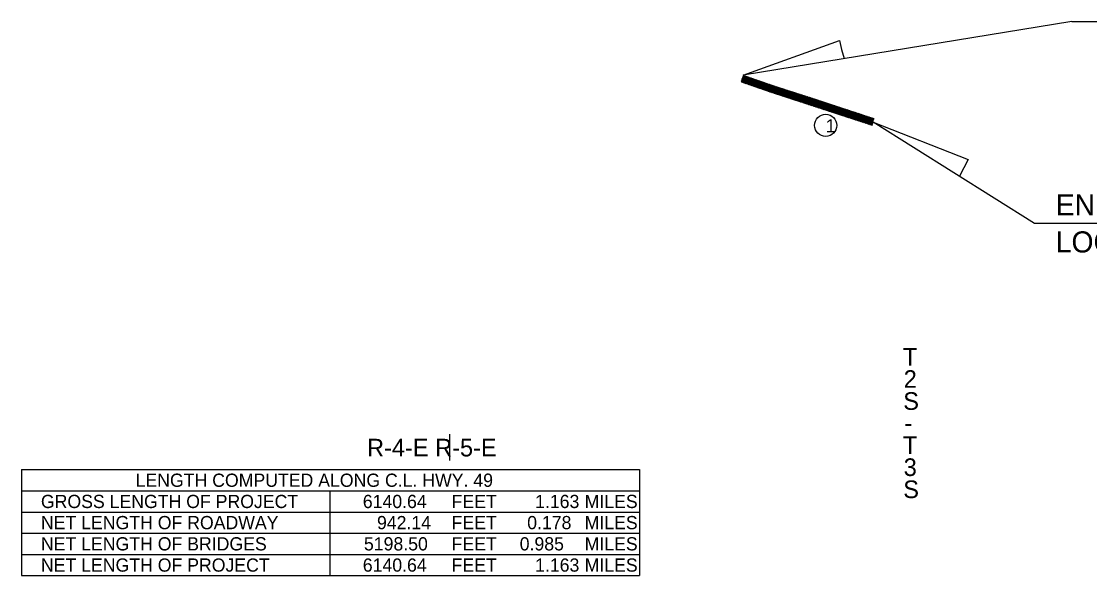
# Model space of a CAD drawing. Extents: x -712 to 3943, y 73 to 2823.
# Drawn here: x 1396 to 2609, y 73 to 702 of the extents above; entities that cross this region are included whole.
import ezdxf

# ---------------------------------------------------------------- set-up
doc = ezdxf.new("R2010")
doc.units = 0
for name, color, linetype in [('2', 7, 'Continuous'), ('3', 7, 'Continuous'), ('Default', 7, 'Continuous'), ('S_MISC_BOUNDARY', 7, 'Continuous')]:
    doc.layers.add(name, color=color, linetype=linetype)

msp = doc.modelspace()

# ---------------------------------------------------------------- linework, layer by layer
at = {"layer": '2'}
msp.add_circle((2309.2, 584.4), 12.6, dxfattribs=at)
at = {"layer": '3'}
for p, q in [((1396.1, 193.6), (1396.1, 73.3)), ((1396.1, 193.6), (2097.8, 193.6)), ((2097.8, 193.6), (2097.8, 73.3)), ((1396.1, 169.6), (2097.8, 169.6)), ((1746.3, 169.6), (1746.3, 73.3)), ((1396.1, 145.5), (2097.8, 145.5)), ((1396.1, 121.4), (2097.8, 121.4)), ((1396.1, 97.4), (2097.8, 97.4)), ((1396.1, 73.3), (2097.8, 73.3))]:
    msp.add_line(p, q, dxfattribs=at)
at = {"layer": 'Default'}
for p, q in [((2863.6, 473.1), (2546.3, 473.1)), ((1882.1, 233.7), (1882.1, 204))]:
    msp.add_line(p, q, dxfattribs=at)
for points in [[(2588.6, 702.5), (2215.6, 641.5), (2324.8, 680.8), (2327.2, 670.6), (2330, 660.2)], [(2588.6, 702.5), (2938.9, 702.3)], [(2546.3, 473.1), (2363, 588.2), (2470.9, 545.5), (2466, 536.2), (2461.2, 526.6)]]:
    msp.add_lwpolyline(points, dxfattribs=at)
at = {"layer": 'S_MISC_BOUNDARY'}
for p, q in [((2213, 633.6), (2219.5, 640.1)), ((2213.2, 634.5), (2219, 640.3)), ((2213.5, 633.4), (2220.1, 639.9)), ((2213.6, 635.6), (2218.5, 640.5)), ((2214, 636.7), (2218, 640.7)), ((2214, 633.2), (2220.6, 639.7)), ((2214.3, 637.7), (2217.4, 640.8)), ((2214.6, 633), (2221.1, 639.6)), ((2214.7, 638.8), (2216.9, 641)), ((2215.1, 639.9), (2216.4, 641.2)), ((2215.1, 632.8), (2221.6, 639.4)), ((2215.5, 641), (2215.9, 641.4)), ((2215.6, 632.6), (2222.2, 639.2)), ((2216.1, 632.5), (2222.7, 639)), ((2216.7, 632.3), (2223.2, 638.8)), ((2217.2, 632.1), (2223.7, 638.6)), ((2217.7, 631.9), (2224.3, 638.5)), ((2218.2, 631.7), (2224.8, 638.3)), ((2218.8, 631.6), (2225.3, 638.1)), ((2219.3, 631.4), (2225.8, 637.9)), ((2219.8, 631.2), (2226.3, 637.7)), ((2220.3, 631), (2226.9, 637.6)), ((2220.9, 630.8), (2227.4, 637.4)), ((2221.4, 630.6), (2227.9, 637.2)), ((2221.9, 630.5), (2228.4, 637)), ((2222.4, 630.3), (2229, 636.8)), ((2223, 630.1), (2229.5, 636.6)), ((2223.5, 629.9), (2230, 636.5)), ((2224, 629.7), (2230.5, 636.3)), ((2224.5, 629.5), (2231.1, 636.1)), ((2225, 629.4), (2231.6, 635.9)), ((2225.6, 629.2), (2232.1, 635.7)), ((2226.1, 629), (2232.6, 635.5)), ((2226.6, 628.8), (2233.2, 635.4)), ((2227.1, 628.6), (2233.7, 635.2)), ((2227.7, 628.4), (2234.2, 635)), ((2228.2, 628.3), (2234.7, 634.8)), ((2228.7, 628.1), (2235.3, 634.6)), ((2229.2, 627.9), (2235.8, 634.4)), ((2229.8, 627.7), (2236.3, 634.3)), ((2230.3, 627.5), (2236.8, 634.1)), ((2230.8, 627.4), (2237.4, 633.9)), ((2231.3, 627.2), (2237.9, 633.7)), ((2231.9, 627), (2238.4, 633.5)), ((2232.4, 626.8), (2238.9, 633.4)), ((2232.9, 626.6), (2239.5, 633.2)), ((2233.4, 626.4), (2240, 633)), ((2234, 626.3), (2240.5, 632.8)), ((2234.5, 626.1), (2241, 632.6)), ((2235, 625.9), (2241.6, 632.4)), ((2235.5, 625.7), (2242.1, 632.3)), ((2236.1, 625.5), (2242.6, 632.1)), ((2236.6, 625.3), (2243.1, 631.9)), ((2237.1, 625.2), (2243.7, 631.7)), ((2237.6, 625), (2244.2, 631.5)), ((2238.2, 624.8), (2244.7, 631.3)), ((2238.7, 624.6), (2245.2, 631.2)), ((2239.2, 624.4), (2245.8, 631)), ((2239.7, 624.3), (2246.3, 630.8)), ((2240.3, 624.1), (2246.8, 630.6)), ((2240.8, 623.9), (2247.3, 630.4)), ((2241.3, 623.7), (2247.9, 630.3)), ((2241.8, 623.5), (2248.4, 630.1)), ((2242.4, 623.3), (2248.9, 629.9)), ((2242.9, 623.2), (2249.4, 629.7)), ((2243.4, 623), (2250, 629.5)), ((2243.9, 622.8), (2250.5, 629.4)), ((2244.5, 622.6), (2251, 629.2)), ((2245, 622.4), (2251.6, 629)), ((2245.5, 622.2), (2252.1, 628.8)), ((2246, 622.1), (2252.6, 628.7)), ((2246.6, 621.9), (2253.2, 628.5)), ((2247.1, 621.7), (2253.7, 628.3)), ((2247.6, 621.5), (2254.2, 628.2)), ((2248.2, 621.4), (2254.8, 628)), ((2248.7, 621.2), (2255.3, 627.8)), ((2249.2, 621), (2255.8, 627.6)), ((2249.8, 620.8), (2256.4, 627.5)), ((2250.3, 620.7), (2256.9, 627.3)), ((2250.8, 620.5), (2257.5, 627.1)), ((2251.4, 620.3), (2258, 626.9)), ((2251.9, 620.1), (2258.5, 626.8)), ((2252.4, 620), (2259.1, 626.6)), ((2253, 619.8), (2259.6, 626.4)), ((2253.5, 619.6), (2260.1, 626.3)), ((2254, 619.4), (2260.7, 626.1)), ((2254.6, 619.3), (2261.2, 625.9)), ((2255.1, 619.1), (2261.7, 625.7)), ((2255.6, 618.9), (2262.3, 625.6)), ((2256.1, 618.7), (2262.8, 625.4)), ((2256.7, 618.6), (2263.3, 625.2)), ((2257.2, 618.4), (2263.9, 625.1)), ((2257.7, 618.2), (2264.4, 624.9)), ((2258.3, 618), (2264.9, 624.7)), ((2258.8, 617.9), (2265.5, 624.5)), ((2259.3, 617.7), (2266, 624.4)), ((2259.9, 617.5), (2266.5, 624.2)), ((2260.4, 617.3), (2267.1, 624)), ((2260.9, 617.2), (2267.6, 623.8)), ((2261.5, 617), (2268.2, 623.7)), ((2262, 616.8), (2268.7, 623.5)), ((2262.5, 616.7), (2269.2, 623.3)), ((2263.1, 616.5), (2269.8, 623.2)), ((2263.6, 616.3), (2270.3, 623)), ((2264.1, 616.1), (2270.8, 622.8)), ((2264.7, 616), (2271.4, 622.6)), ((2265.2, 615.8), (2271.9, 622.5)), ((2265.7, 615.6), (2272.4, 622.3)), ((2266.3, 615.4), (2273, 622.1)), ((2266.8, 615.3), (2273.5, 622)), ((2267.3, 615.1), (2274, 621.8)), ((2267.9, 614.9), (2274.6, 621.6)), ((2268.4, 614.7), (2275.1, 621.4)), ((2268.9, 614.6), (2275.6, 621.3)), ((2269.5, 614.4), (2276.2, 621.1)), ((2270, 614.2), (2276.7, 620.9)), ((2270.5, 614), (2277.2, 620.7)), ((2271.1, 613.9), (2277.8, 620.6)), ((2271.6, 613.7), (2278.3, 620.4)), ((2272.1, 613.5), (2278.8, 620.2)), ((2272.7, 613.3), (2279.4, 620.1)), ((2273.2, 613.2), (2279.9, 619.9)), ((2273.7, 613), (2280.5, 619.7)), ((2274.3, 612.8), (2281, 619.5)), ((2274.8, 612.6), (2281.5, 619.4)), ((2275.3, 612.5), (2282.1, 619.2)), ((2275.9, 612.3), (2282.6, 619)), ((2276.4, 612.1), (2283.1, 618.9)), ((2276.9, 612), (2283.7, 618.7)), ((2277.5, 611.8), (2284.2, 618.5)), ((2278, 611.6), (2284.7, 618.3)), ((2278.5, 611.4), (2285.3, 618.2)), ((2279.1, 611.3), (2285.8, 618)), ((2279.6, 611.1), (2286.3, 617.8)), ((2280.1, 610.9), (2286.9, 617.6)), ((2280.7, 610.7), (2287.4, 617.5)), ((2281.2, 610.6), (2287.9, 617.3)), ((2281.7, 610.4), (2288.5, 617.1)), ((2282.3, 610.2), (2289, 617)), ((2282.8, 610), (2289.5, 616.8)), ((2283.3, 609.9), (2290.1, 616.6)), ((2283.9, 609.7), (2290.6, 616.4)), ((2284.4, 609.5), (2291.2, 616.3)), ((2284.9, 609.3), (2291.7, 616.1)), ((2285.5, 609.2), (2292.2, 615.9)), ((2286, 609), (2292.8, 615.8)), ((2286.5, 608.8), (2293.3, 615.6)), ((2287.1, 608.6), (2293.8, 615.4)), ((2287.6, 608.5), (2294.4, 615.2)), ((2288.1, 608.3), (2294.9, 615.1)), ((2288.7, 608.1), (2295.4, 614.9)), ((2289.2, 607.9), (2296, 614.7)), ((2289.7, 607.8), (2296.5, 614.5)), ((2290.3, 607.6), (2297, 614.4)), ((2290.8, 607.4), (2297.6, 614.2)), ((2291.3, 607.2), (2298.1, 614)), ((2291.9, 607.1), (2298.6, 613.8)), ((2292.4, 606.9), (2299.2, 613.7)), ((2292.9, 606.7), (2299.7, 613.5)), ((2293.5, 606.6), (2300.2, 613.3)), ((2294, 606.4), (2300.8, 613.1)), ((2294.5, 606.2), (2301.3, 613)), ((2295.1, 606), (2301.8, 612.8)), ((2295.6, 605.9), (2302.3, 612.6)), ((2296.1, 605.7), (2302.9, 612.4)), ((2296.7, 605.5), (2303.4, 612.3)), ((2297.2, 605.3), (2303.9, 612.1)), ((2297.7, 605.2), (2304.5, 611.9)), ((2298.3, 605), (2305, 611.7)), ((2298.8, 604.8), (2305.5, 611.6)), ((2299.3, 604.6), (2306.1, 611.4)), ((2299.9, 604.5), (2306.6, 611.2)), ((2300.4, 604.3), (2307.1, 611)), ((2300.9, 604.1), (2307.7, 610.9)), ((2301.5, 603.9), (2308.2, 610.7)), ((2302, 603.8), (2308.7, 610.5)), ((2302.5, 603.6), (2309.3, 610.3)), ((2303.1, 603.4), (2309.8, 610.2)), ((2303.6, 603.2), (2310.3, 610)), ((2304.1, 603.1), (2310.9, 609.8)), ((2304.7, 602.9), (2311.4, 609.6)), ((2305.2, 602.7), (2311.9, 609.5)), ((2305.7, 602.5), (2312.4, 609.3)), ((2306.2, 602.4), (2313, 609.1)), ((2306.8, 602.2), (2313.5, 608.9)), ((2307.3, 602), (2314, 608.8)), ((2307.8, 601.9), (2314.6, 608.6)), ((2308.4, 601.7), (2315.1, 608.4)), ((2308.9, 601.5), (2315.6, 608.2)), ((2309.4, 601.3), (2316.2, 608.1)), ((2310, 601.2), (2316.7, 607.9)), ((2310.5, 601), (2317.2, 607.7)), ((2311, 600.8), (2317.8, 607.5)), ((2311.6, 600.6), (2318.3, 607.4)), ((2312.1, 600.5), (2318.8, 607.2)), ((2312.6, 600.3), (2319.4, 607)), ((2313.2, 600.1), (2319.9, 606.8)), ((2313.7, 599.9), (2320.4, 606.6)), ((2314.2, 599.8), (2321, 606.5)), ((2314.8, 599.6), (2321.5, 606.3)), ((2315.3, 599.4), (2322, 606.1)), ((2315.8, 599.2), (2322.5, 605.9)), ((2316.4, 599.1), (2323.1, 605.8)), ((2316.9, 598.9), (2323.6, 605.6)), ((2317.4, 598.7), (2324.1, 605.4)), ((2318, 598.5), (2324.7, 605.2)), ((2318.5, 598.4), (2325.2, 605.1)), ((2319, 598.2), (2325.7, 604.9)), ((2319.6, 598), (2326.3, 604.7)), ((2320.1, 597.8), (2326.8, 604.5)), ((2320.6, 597.7), (2327.3, 604.4)), ((2321.2, 597.5), (2327.9, 604.2)), ((2321.7, 597.3), (2328.4, 604)), ((2322.2, 597.2), (2328.9, 603.8)), ((2322.8, 597), (2329.5, 603.7)), ((2323.3, 596.8), (2330, 603.5)), ((2323.8, 596.6), (2330.5, 603.3)), ((2324.4, 596.5), (2331.1, 603.1)), ((2324.9, 596.3), (2331.6, 603)), ((2325.4, 596.1), (2332.1, 602.8)), ((2326, 595.9), (2332.7, 602.6)), ((2326.5, 595.8), (2333.2, 602.4)), ((2327, 595.6), (2333.7, 602.3)), ((2327.6, 595.4), (2334.2, 602.1)), ((2328.1, 595.2), (2334.8, 601.9)), ((2328.6, 595.1), (2335.3, 601.7)), ((2329.2, 594.9), (2335.8, 601.6)), ((2329.7, 594.7), (2336.4, 601.4)), ((2330.2, 594.5), (2336.9, 601.2)), ((2330.8, 594.4), (2337.4, 601)), ((2331.3, 594.2), (2338, 600.9)), ((2331.8, 594), (2338.5, 600.7)), ((2332.4, 593.8), (2339, 600.5)), ((2332.9, 593.7), (2339.6, 600.3)), ((2333.4, 593.5), (2340.1, 600.2)), ((2334, 593.3), (2340.6, 600)), ((2334.5, 593.1), (2341.2, 599.8)), ((2335, 593), (2341.7, 599.6)), ((2335.6, 592.8), (2342.2, 599.5)), ((2336.1, 592.6), (2342.8, 599.3)), ((2336.6, 592.4), (2343.3, 599.1)), ((2337.2, 592.3), (2343.8, 598.9)), ((2337.7, 592.1), (2344.3, 598.8)), ((2338.2, 591.9), (2344.9, 598.6)), ((2338.8, 591.8), (2345.4, 598.4)), ((2339.3, 591.6), (2345.9, 598.2)), ((2339.8, 591.4), (2346.5, 598.1)), ((2340.4, 591.2), (2347, 597.9)), ((2340.9, 591.1), (2347.5, 597.7)), ((2341.4, 590.9), (2348.1, 597.5)), ((2342, 590.7), (2348.6, 597.4)), ((2342.5, 590.5), (2349.1, 597.2)), ((2343, 590.4), (2349.7, 597)), ((2343.6, 590.2), (2350.2, 596.8)), ((2344.1, 590), (2350.7, 596.6)), ((2344.6, 589.8), (2351.3, 596.5)), ((2345.2, 589.7), (2351.8, 596.3)), ((2345.7, 589.5), (2352.3, 596.1)), ((2346.2, 589.3), (2352.9, 595.9)), ((2346.8, 589.1), (2353.4, 595.8)), ((2347.3, 589), (2353.9, 595.6)), ((2347.8, 588.8), (2354.5, 595.4)), ((2348.4, 588.6), (2355, 595.2)), ((2348.9, 588.4), (2355.5, 595.1)), ((2349.4, 588.3), (2356, 594.9)), ((2350, 588.1), (2356.6, 594.7)), ((2350.5, 587.9), (2357.1, 594.5)), ((2351, 587.7), (2357.6, 594.4)), ((2351.6, 587.6), (2358.2, 594.2)), ((2352.1, 587.4), (2358.7, 594)), ((2352.6, 587.2), (2359.2, 593.8)), ((2353.2, 587.1), (2359.8, 593.7)), ((2353.7, 586.9), (2360.3, 593.5)), ((2354.2, 586.7), (2360.8, 593.3)), ((2354.8, 586.5), (2361.4, 593.1)), ((2355.3, 586.4), (2361.9, 593)), ((2355.8, 586.2), (2362.4, 592.8)), ((2356.3, 586), (2363, 592.6)), ((2356.9, 585.8), (2363.5, 592.4)), ((2357.4, 585.7), (2364, 592.2)), ((2357.9, 585.5), (2363.7, 591.3)), ((2358.5, 585.3), (2363.5, 590.3)), ((2359, 585.1), (2363.2, 589.3)), ((2359.5, 585), (2363, 588.4)), ((2360.1, 584.8), (2362.7, 587.4)), ((2360.6, 584.6), (2362.5, 586.5)), ((2361.1, 584.4), (2362.2, 585.5)), ((2361.7, 584.3), (2362, 584.6))]:
    msp.add_line(p, q, dxfattribs=at)

# ---------------------------------------------------------------- texts
at = {"layer": '2'}
msp.add_text('1', height=15, dxfattribs=at).set_placement((2309.2, 576.4))
at = {"layer": '3'}
for s, p in [('LENGTH COMPUTED ALONG C.L. HWY. 49', (1525.8, 174.1)), ('GROSS LENGTH OF PROJECT', (1418.3, 150)), ('6140.64', (1783.7, 150)), ('FEET', (1884.5, 150)), ('1.163', (1979.3, 150)), ('MILES', (2035.5, 150)), ('NET LENGTH OF ROADWAY', (1418.3, 126)), ('942.14', (1799.8, 126)), ('FEET', (1884.5, 126)), ('0.178', (1970.3, 126)), ('MILES', (2035.5, 126)), ('NET LENGTH OF BRIDGES', (1418.3, 101.9)), ('5198.50', (1785, 101.9)), ('FEET', (1884.5, 101.9)), ('0.985', (1961.8, 101.9)), ('MILES', (2035.5, 101.9)), ('NET LENGTH OF PROJECT', (1418.3, 77.8)), ('6140.64', (1783.7, 77.8)), ('FEET', (1884.5, 77.8)), ('1.163', (1979.3, 77.8)), ('MILES', (2035.5, 77.8))]:
    msp.add_text(s, height=15, dxfattribs=at).set_placement(p)
at = {"layer": 'Default'}
for s, height, p in [('END JOB 110812', 24, (2570.3, 482.1)), ('LOG MILE 1.706', 24, (2570.3, 440.1)), ('T', 20, (2396.8, 311.6)), ('2', 20, (2397.7, 286.5)), ('S', 20, (2397.2, 261.5)), ('-', 20, (2398.5, 236.5)), ('T', 20, (2396.8, 211.4)), ('R-4-E R-5-E', 20, (1788.5, 208.6)), ('3', 20, (2397.7, 186.4)), ('S', 20, (2397.2, 161.3))]:
    msp.add_text(s, height=height, dxfattribs=at).set_placement(p)

doc.saveas('drawing.dxf')
